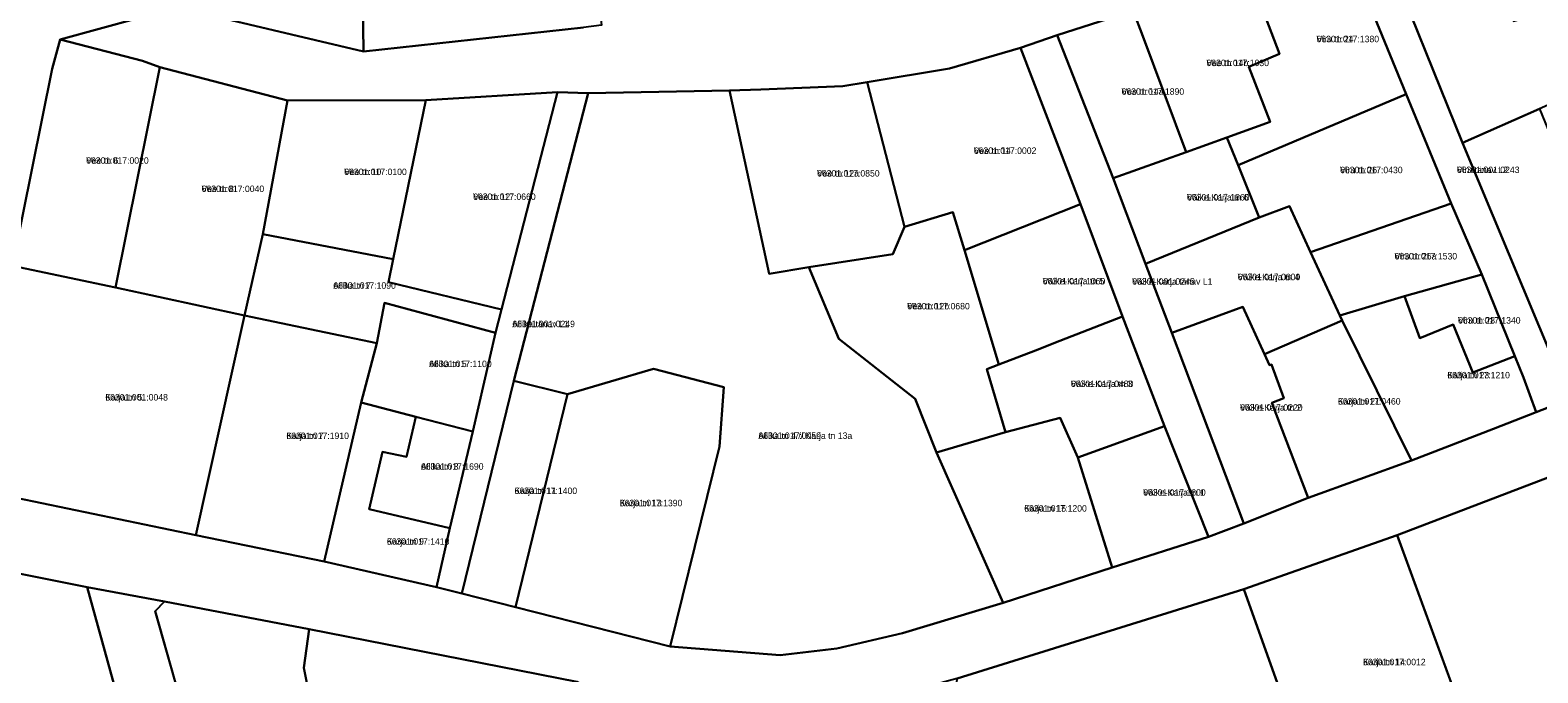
# Model space of a CAD drawing. Extents: x 632278 to 636344, y 6578401 to 6583362.
# Drawn here: x 634226.1 to 634575.5, y 6580128.4 to 6580277.2 of the extents above; entities that cross this region are included whole.
import ezdxf

# ---------------------------------------------------------------- set-up
doc = ezdxf.new("R2010")
doc.units = 0
for name, color, linetype in [('L_AADRESS', 7, 'Continuous'), ('PIIR', 7, 'Continuous'), ('TUNNUS', 7, 'Continuous')]:
    doc.layers.add(name, color=color, linetype=linetype)

msp = doc.modelspace()

# ---------------------------------------------------------------- linework, layer by layer
at = {"layer": 'PIIR'}
for points in [[(634225.23, 6581067.6), (634226.68, 6581036.58), (634227.15, 6581025.28), (634228.16, 6581005.67), (634228.8, 6580993.57), (634229.91, 6580974.72), (634244.55, 6580754.47), (634246.36, 6580732.87), (634249.81, 6580666.52), (634250.81, 6580645.38), (634251.04, 6580641.51), (634252.34, 6580620.25), (634253.83, 6580589.78), (634265.55, 6580590.45), (634266.51, 6580570.25), (634267.07, 6580555.4), (634269.03, 6580516.69), (634274.45, 6580483.07), (634276.55, 6580470.05), (634283.11, 6580360.46), (634260.23, 6580282.49), (634233.12, 6580275.05), (634231.27, 6580268.29), (634222.04, 6580222.66)], [(634481.72, 6580281.73), (634464.09, 6580276.05), (634455.6, 6580273.18), (634439.14, 6580268.37), (634420.13, 6580265.24), (634414.46, 6580264.28), (634395.42, 6580263.51), (634388.22, 6580263.25), (634355.47, 6580262.66), (634348.35, 6580262.91), (634317.79, 6580261.01), (634285.8, 6580260.98), (634256.19, 6580268.71), (634252.21, 6580270.17), (634233.12, 6580275.05), (634260.23, 6580282.49), (634303.37, 6580272.33), (634354.37, 6580277.83)], [(634796.84, 6580256.64), (634781.1, 6580253.3), (634732.12, 6580233.33), (634708.48, 6580224.14), (634704.91, 6580222.83), (634676.03, 6580211.71), (634647.97, 6580200.86), (634620.2, 6580190.27), (634596.17, 6580180.31), (634578.31, 6580173.81), (634542.88, 6580160.31), (634507.37, 6580147.83), (634440.93, 6580127.14), (634436.12, 6580125.78), (634405.48, 6580117.09), (634379.51, 6580118.32), (634377.21, 6580117.77), (634370.68, 6580115.86), (634352.92, 6580126.39), (634290.76, 6580138.56), (634257.24, 6580144.92), (634239.36, 6580148.28), (634207.95, 6580154.5)], [(634216.85, 6580170.18), (634264.55, 6580160.32), (634294.23, 6580154.19), (634320.27, 6580148.28), (634326.13, 6580146.83), (634338.64, 6580143.65), (634374.46, 6580134.54), (634399.91, 6580132.57), (634413.04, 6580134.06), (634428.25, 6580137.64), (634451.61, 6580144.66), (634476.85, 6580152.86), (634499.2, 6580159.96), (634507.35, 6580163.04), (634522.28, 6580168.97), (634546.25, 6580177.6), (634565.25, 6580184.94), (634575.12, 6580188.79), (634582.82, 6580191.82)], [(634309.43, 6579898.1), (634297.75, 6579941.29), (634295.22, 6579949.63), (634282.85, 6579992.64), (634279.74, 6580004.23), (634277, 6580013.79), (634274.94, 6580020.93), (634270.74, 6580035.47), (634259.44, 6580075.27), (634258.41, 6580079.17), (634239.36, 6580148.28), (634257.24, 6580144.92), (634255.11, 6580142.72), (634267.8, 6580097.86), (634272.74, 6580080.88), (634284.74, 6580039.26), (634297.36, 6579994.9), (634309.55, 6579952.52), (634312.1, 6579944.67), (634318.74, 6579919.57), (634326.8, 6579890.54)]]:
    msp.add_lwpolyline(points, dxfattribs=at)
for points in [[(634283.11, 6580360.46), (634293.57, 6580364.44), (634312.47, 6580371.55), (634314.27, 6580368.32), (634318.31, 6580360.16), (634321.64, 6580351.43), (634326.09, 6580345.26), (634331.55, 6580335.58), (634329.35, 6580328.55), (634332.63, 6580322.9), (634336.65, 6580321.94), (634340.66, 6580322.67), (634344.43, 6580322.96), (634346.85, 6580320.89), (634348.72, 6580317.96), (634336.36, 6580314.86), (634302.95, 6580306.26), (634303.37, 6580272.33), (634260.23, 6580282.49)], [(634302.95, 6580306.26), (634336.36, 6580314.86), (634348.72, 6580317.96), (634349.53, 6580307.22), (634355.4, 6580298.27), (634357.56, 6580287.01), (634358.57, 6580278.43), (634354.37, 6580277.83), (634303.37, 6580272.33)], [(634541.41, 6580301.26), (634560.67, 6580307.3), (634569.85, 6580279.3), (634590.83, 6580285.49), (634593.56, 6580278.61), (634589.83, 6580277.07), (634593.65, 6580266.88), (634584.49, 6580262.83), (634575.89, 6580259.01), (634558.06, 6580251.13), (634539.28, 6580297.69)], [(634530.69, 6580297.31), (634541.41, 6580301.26), (634539.28, 6580297.69), (634558.06, 6580251.13), (634582.82, 6580191.82), (634575.12, 6580188.79), (634572.15, 6580196.8), (634570.15, 6580201.73), (634562.5, 6580220.65), (634555.39, 6580237.12), (634545.01, 6580262.39)], [(634503.41, 6580252.42), (634513.48, 6580256.03), (634508.53, 6580268.79), (634515.67, 6580271.8), (634508.64, 6580290.29), (634530.69, 6580297.31), (634545.01, 6580262.39), (634506.08, 6580246.02)], [(634508.64, 6580290.29), (634515.67, 6580271.8), (634508.53, 6580268.79), (634513.48, 6580256.03), (634503.41, 6580252.42), (634494, 6580249.01), (634483.94, 6580275.88), (634481.72, 6580281.73)], [(634464.09, 6580276.05), (634481.72, 6580281.73), (634483.94, 6580275.88), (634494, 6580249.01), (634477.06, 6580242.99)], [(634455.6, 6580273.18), (634464.09, 6580276.05), (634477.06, 6580242.99), (634484.61, 6580223.17), (634490.7, 6580207.2), (634507.35, 6580163.04), (634499.2, 6580159.96), (634488.96, 6580185.53), (634479.29, 6580210.94), (634469.49, 6580236.94)], [(634252.21, 6580270.17), (634256.19, 6580268.71), (634245.94, 6580217.68), (634222.04, 6580222.66), (634231.27, 6580268.29), (634233.12, 6580275.05)], [(634420.13, 6580265.24), (634439.14, 6580268.37), (634455.6, 6580273.18), (634469.49, 6580236.94), (634442.68, 6580226.31), (634439.94, 6580235.08), (634428.75, 6580231.68)], [(634256.19, 6580268.71), (634285.8, 6580260.98), (634280.02, 6580229.98), (634275.82, 6580211.18), (634245.94, 6580217.68)], [(634397.35, 6580220.85), (634388.22, 6580263.25), (634395.42, 6580263.51), (634414.46, 6580264.28), (634420.13, 6580265.24), (634428.75, 6580231.68), (634426.02, 6580225.39), (634406.61, 6580222.36)], [(634310.28, 6580224.21), (634317.79, 6580261.01), (634348.35, 6580262.91), (634335.39, 6580212.56), (634309.2, 6580218.91)], [(634348.35, 6580262.91), (634355.47, 6580262.66), (634338.18, 6580196.02), (634326.13, 6580146.83), (634320.27, 6580148.28), (634323.38, 6580161.96), (634328.71, 6580184.32), (634333.95, 6580207.13), (634335.39, 6580212.56)], [(634388.22, 6580263.25), (634397.35, 6580220.85), (634406.61, 6580222.36), (634413.51, 6580205.75), (634431.18, 6580191.9), (634436.13, 6580179.48), (634451.61, 6580144.66), (634428.25, 6580137.64), (634413.04, 6580134.06), (634399.91, 6580132.57), (634374.46, 6580134.54), (634385.84, 6580180.83), (634386.91, 6580194.59), (634370.6, 6580198.82), (634350.65, 6580192.94), (634338.18, 6580196.02), (634355.47, 6580262.66)], [(634522.81, 6580225.86), (634517.93, 6580236.48), (634510.9, 6580233.84), (634506.08, 6580246.02), (634545.01, 6580262.39), (634555.39, 6580237.12)], [(634285.8, 6580260.98), (634317.79, 6580261.01), (634310.28, 6580224.21), (634280.02, 6580229.98)], [(634575.89, 6580259.01), (634591.83, 6580220.26), (634598.31, 6580205.46), (634600.93, 6580198.68), (634582.82, 6580191.82), (634558.06, 6580251.13)], [(634477.06, 6580242.99), (634494, 6580249.01), (634503.41, 6580252.42), (634506.08, 6580246.02), (634510.9, 6580233.84), (634484.61, 6580223.17)], [(634413.51, 6580205.75), (634406.61, 6580222.36), (634426.02, 6580225.39), (634428.75, 6580231.68), (634439.94, 6580235.08), (634442.68, 6580226.31), (634450.62, 6580199.8), (634447.86, 6580198.74), (634452.13, 6580184.17), (634436.13, 6580179.48), (634431.18, 6580191.9)], [(634450.62, 6580199.8), (634442.68, 6580226.31), (634469.49, 6580236.94), (634479.29, 6580210.94), (634464.74, 6580205.31), (634459.09, 6580203.09)], [(634484.61, 6580223.17), (634510.9, 6580233.84), (634517.93, 6580236.48), (634522.81, 6580225.86), (634529.65, 6580211.18), (634530.18, 6580210.05), (634512.13, 6580202.22), (634507.13, 6580213.18), (634490.7, 6580207.2)], [(634522.81, 6580225.86), (634555.39, 6580237.12), (634562.5, 6580220.65), (634544.61, 6580215.63), (634529.65, 6580211.18)], [(634280.02, 6580229.98), (634310.28, 6580224.21), (634309.2, 6580218.91), (634335.39, 6580212.56), (634333.95, 6580207.13), (634308.25, 6580214.13), (634306.47, 6580204.76), (634275.82, 6580211.18)], [(634212.81, 6580177.57), (634222.04, 6580222.66), (634245.94, 6580217.69), (634275.82, 6580211.18), (634264.55, 6580160.32), (634216.85, 6580170.18), (634213.76, 6580173.99)], [(634544.61, 6580215.63), (634562.5, 6580220.65), (634570.15, 6580201.73), (634560.44, 6580197.95), (634555.87, 6580209.12), (634548.13, 6580205.95)], [(634302.88, 6580191.02), (634306.47, 6580204.76), (634308.25, 6580214.13), (634333.95, 6580207.13), (634328.71, 6580184.32), (634315.54, 6580187.73)], [(634507.13, 6580213.18), (634512.13, 6580202.22), (634513.29, 6580199.67), (634513.77, 6580199.87), (634516.64, 6580192), (634513.84, 6580190.97), (634522.28, 6580168.97), (634507.35, 6580163.04), (634490.7, 6580207.2)], [(634530.18, 6580210.05), (634529.65, 6580211.18), (634544.61, 6580215.63), (634548.13, 6580205.95), (634555.87, 6580209.12), (634560.44, 6580197.95), (634570.15, 6580201.73), (634572.15, 6580196.8), (634575.12, 6580188.79), (634565.25, 6580184.94), (634546.25, 6580177.6)], [(634275.82, 6580211.18), (634306.47, 6580204.76), (634302.88, 6580191.02), (634294.23, 6580154.19), (634264.55, 6580160.32)], [(634468.88, 6580178.28), (634464.83, 6580187.45), (634452.13, 6580184.17), (634447.86, 6580198.74), (634450.62, 6580199.8), (634459.09, 6580203.09), (634464.74, 6580205.31), (634479.29, 6580210.94), (634488.96, 6580185.53)], [(634513.84, 6580190.97), (634516.64, 6580192), (634513.77, 6580199.87), (634513.29, 6580199.67), (634512.13, 6580202.22), (634530.18, 6580210.05), (634546.25, 6580177.6), (634522.28, 6580168.97)], [(634350.65, 6580192.94), (634370.6, 6580198.82), (634386.91, 6580194.59), (634385.84, 6580180.83), (634374.46, 6580134.54), (634338.64, 6580143.65)], [(634338.18, 6580196.02), (634350.65, 6580192.94), (634338.64, 6580143.65), (634326.13, 6580146.83)], [(634302.88, 6580191.02), (634315.54, 6580187.73), (634313.36, 6580178.44), (634307.78, 6580179.63), (634304.68, 6580166.3), (634323.38, 6580161.96), (634320.27, 6580148.28), (634294.23, 6580154.19)], [(634307.78, 6580179.63), (634313.36, 6580178.44), (634315.54, 6580187.73), (634328.71, 6580184.32), (634323.38, 6580161.96), (634304.68, 6580166.3)], [(634436.13, 6580179.48), (634452.13, 6580184.17), (634464.83, 6580187.45), (634468.88, 6580178.28), (634476.85, 6580152.86), (634451.61, 6580144.66)], [(634468.88, 6580178.28), (634488.96, 6580185.53), (634499.2, 6580159.96), (634476.85, 6580152.86)], [(634561.45, 6580109.75), (634542.88, 6580160.31), (634578.31, 6580173.81), (634609.25, 6580093.13), (634611.9, 6580086.21), (634606.27, 6580088.9), (634591.53, 6580095.77), (634581.47, 6580099.94), (634562.64, 6580106.5)], [(634160.64, 6580107.9), (634152.7, 6580136.01), (634150.93, 6580143.48), (634151.81, 6580146.37), (634158.78, 6580160.81), (634160.14, 6580162.23), (634162.35, 6580162.98), (634164.18, 6580163.05), (634181.44, 6580159.69), (634207.95, 6580154.5), (634239.36, 6580148.28), (634258.41, 6580079.17), (634219.59, 6580068.6), (634194.26, 6580061.37), (634174.58, 6580109.77)], [(634525.63, 6580096.76), (634507.37, 6580147.83), (634542.88, 6580160.31), (634562.64, 6580106.5), (634552.34, 6580107.85), (634542.5, 6580105.71), (634531.48, 6580101.52)], [(634440.93, 6580127.14), (634507.37, 6580147.83), (634525.63, 6580096.76), (634527.43, 6580090.65), (634542.3, 6580045.83), (634536.85, 6580044.2), (634531.13, 6580061.26), (634524.07, 6580082.23), (634489.51, 6580084.71), (634459.8, 6580094.28), (634439.94, 6580097.78), (634436.84, 6580102.99), (634439.98, 6580113.4)], [(634257.24, 6580144.92), (634290.76, 6580138.56), (634289.57, 6580129.63), (634291.91, 6580118.12), (634294.9, 6580103.08), (634267.8, 6580097.86), (634260.54, 6580123.73), (634255.11, 6580142.72)], [(634307.91, 6580121.76), (634291.91, 6580118.12), (634289.57, 6580129.63), (634290.76, 6580138.56), (634352.92, 6580126.39), (634360.92, 6580096.91), (634317.52, 6580089.17)]]:
    msp.add_lwpolyline(points, close=True, dxfattribs=at)

# ---------------------------------------------------------------- texts
at = {"layer": 'L_AADRESS'}
for s, p in [('Viru tn 24', (634524.21, 6580274.45)), ('Vee tn 14b', (634498.7, 6580268.92)), ('Vee tn 14a', (634479.05, 6580262.28)), ('Vee tn 6', (634239.11, 6580246.31)), ('Vee tn 14', (634444.81, 6580248.59)), ('Vee tn 10', (634298.91, 6580243.69)), ('Vee tn 12a', (634408.48, 6580243.35)), ('Viru tn 26', (634529.67, 6580244.12)), ('Viru tänav L2', (634556.75, 6580244.16)), ('Vee tn 8', (634265.87, 6580239.76)), ('Vee tn 12', (634328.78, 6580237.93)), ('Väike-Karja tn 6', (634494.19, 6580237.8)), ('Viru tn 26a', (634542.3, 6580224.15)), ('Väike-Karja tn 5', (634460.77, 6580218.37)), ('Väike-Karja tänav L1', (634481.48, 6580218.3)), ('Väike-Karja tn 4', (634505.95, 6580219.35)), ('Allika tn 7', (634296.38, 6580217.37)), ('Vee tn 12b', (634429.37, 6580212.59)), ('Allika tänav L1', (634337.87, 6580208.47)), ('Viru tn 28', (634557, 6580209.3)), ('Allika tn 5', (634318.58, 6580199.23)), ('Väike-Karja tn 3', (634467.29, 6580194.61)), ('Karja tn 23', (634554.53, 6580196.62)), ('Karja tn 5', (634243.56, 6580191.49)), ('Karja tn 21', (634529.19, 6580190.54)), ('Väike-Karja tn 2', (634506.49, 6580189.13)), ('Karja tn 7', (634285.51, 6580182.57)), ('Allika tn 4 // Karja tn 13a', (634394.89, 6580182.6)), ('Allika tn 3', (634316.7, 6580175.47)), ('Karja tn 11', (634338.39, 6580169.84)), ('Väike-Karja tn 1', (634484.04, 6580169.45)), ('Karja tn 13', (634362.77, 6580167.01)), ('Karja tn 15', (634456.49, 6580165.77)), ('Karja tn 9', (634308.8, 6580158.11)), ('Karja tn 14', (634535, 6580130.2))]:
    msp.add_text(s, height=1.5, dxfattribs=at).set_placement(p)
at = {"layer": 'TUNNUS'}
for s, p in [('66301:017:1380', (634524.21, 6580274.45)), ('66301:017:1030', (634498.7, 6580268.92)), ('66301:017:1890', (634479.05, 6580262.28)), ('66301:017:0020', (634239.11, 6580246.31)), ('66301:017:0002', (634444.81, 6580248.59)), ('66301:017:0100', (634298.91, 6580243.69)), ('66301:017:0850', (634408.48, 6580243.35)), ('66301:017:0430', (634529.67, 6580244.12)), ('66301:001:0243', (634556.75, 6580244.16)), ('66301:017:0040', (634265.87, 6580239.76)), ('66301:017:0660', (634328.78, 6580237.93)), ('66301:017:1660', (634494.19, 6580237.8)), ('66301:017:1530', (634542.3, 6580224.15)), ('66301:017:1060', (634460.77, 6580218.37)), ('66301:001:0245', (634481.48, 6580218.3)), ('66301:017:0600', (634505.95, 6580219.35)), ('66301:017:1090', (634296.38, 6580217.37)), ('66301:017:0680', (634429.37, 6580212.59)), ('66301:001:0249', (634337.87, 6580208.47)), ('66301:017:1340', (634557, 6580209.3)), ('66301:017:1100', (634318.58, 6580199.23)), ('66301:017:0480', (634467.29, 6580194.61)), ('66301:017:1210', (634554.53, 6580196.62)), ('66301:001:0048', (634243.56, 6580191.49)), ('66301:017:0460', (634529.19, 6580190.54)), ('66301:017:0220', (634506.49, 6580189.13)), ('66301:017:1910', (634285.51, 6580182.57)), ('66301:017:0059', (634394.89, 6580182.6)), ('66301:017:1690', (634316.7, 6580175.47)), ('66301:017:1400', (634338.39, 6580169.84)), ('66301:017:1600', (634484.04, 6580169.45)), ('66301:017:1390', (634362.77, 6580167.01)), ('66301:017:1200', (634456.49, 6580165.77)), ('66301:017:1410', (634308.8, 6580158.11)), ('66301:017:0012', (634535, 6580130.2))]:
    msp.add_text(s, height=1.5, dxfattribs=at).set_placement(p)

doc.saveas('drawing.dxf')
